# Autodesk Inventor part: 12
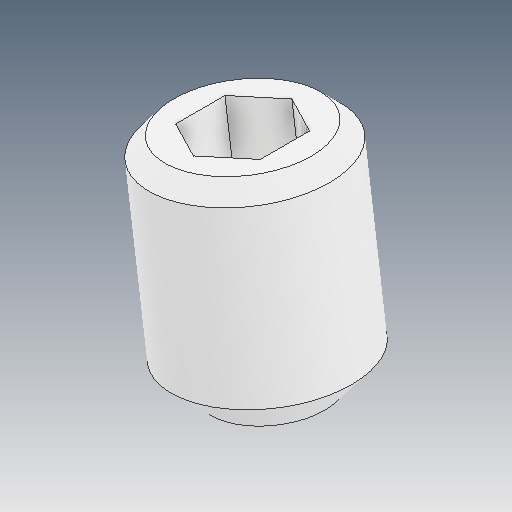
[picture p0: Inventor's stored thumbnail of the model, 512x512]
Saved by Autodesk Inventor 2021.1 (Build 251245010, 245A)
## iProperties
Created: 2021-06
Part Number: 12
Material: Ogólny
Document SubType Name: Modeling
Designer: user
Density: 1 g/cm^3
Appearance: Domyślna
Author: user
Revision Number: ÈÎºÎ
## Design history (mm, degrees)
feature "ÊäÈë1"
node "Bryła1"
